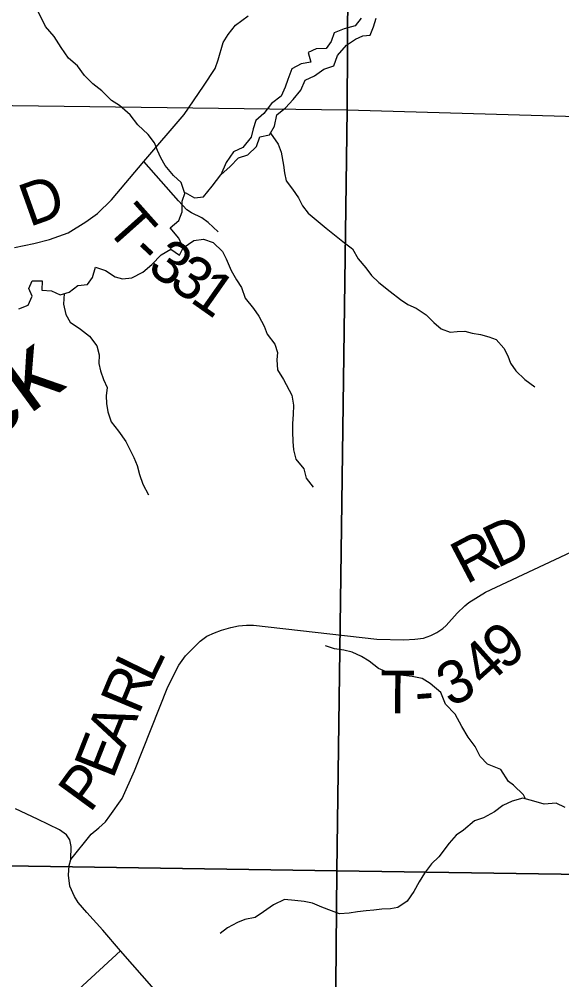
# Model space of a CAD drawing. Extents: x -3.6 to 34, y 0 to 32.8.
# Drawn here: x 0.835 to 1.556, y 30.853 to 32.129 of the extents above; entities that cross this region are included whole.
import ezdxf

# ---------------------------------------------------------------- set-up
doc = ezdxf.new("R2010")
doc.units = 0
for name, color, linetype in [('GM_X_Corporation', 7, 'Continuous'), ('GM_X_County_Road', 7, 'Continuous'), ('GM_X_County_Road_Text', 7, 'Continuous'), ('GM_X_Minor_River', 7, 'Continuous'), ('GM_X_Minor_River_Text', 7, 'Continuous'), ('GM_X_State_Route', 7, 'Continuous'), ('GM_X_Township_Road', 7, 'Continuous'), ('GM_X_Township_Road_Text', 7, 'Continuous')]:
    doc.layers.add(name, color=color, linetype=linetype)

msp = doc.modelspace()

# ---------------------------------------------------------------- linework, layer by layer
at = {"layer": 'GM_X_Corporation'}
for points in [[(1.2753, 32.8429), (0.2894, 32.8429), (0.2807, 32.0992), (0.279, 32.0211), (1.2712, 32.0083)], [(2.2831, 32.8429), (1.2753, 32.8429), (1.2712, 32.0083), (2.2789, 31.9792)], [(0.279, 32.0211), (1.2712, 32.0083), (1.2573, 30.9978), (0.262, 31.0128), (0.2635, 31.0982)], [(1.2712, 32.0083), (2.2789, 31.9792), (2.27, 30.9827), (1.2573, 30.9978)], [(0.262, 31.0128), (1.2573, 30.9978), (1.2483, 29.9822), (0.244, 29.9924), (0.2459, 30.0789)], [(1.2573, 30.9978), (2.27, 30.9827), (2.2535, 29.9602), (1.2483, 29.9822)]]:
    msp.add_lwpolyline(points, close=True, dxfattribs=at)
at = {"layer": 'GM_X_County_Road'}
for points in [[(0.8292, 31.8255), (0.855, 31.8306), (0.8758, 31.8359), (0.9004, 31.8451), (0.9237, 31.8597), (0.9395, 31.8706), (0.9578, 31.8888), (1.001, 31.9395), (1.0545, 32.0021), (1.0804, 32.0395), (1.0955, 32.063), (1.0995, 32.0745), (1.1063, 32.0978), (1.1129, 32.1082), (1.1226, 32.1205), (1.1394, 32.133)], [(0.8918, 30.82), (0.9701, 30.8915)]]:
    msp.add_lwpolyline(points, dxfattribs=at)
at = {"layer": 'GM_X_Minor_River'}
for points in [[(1.0555, 31.8971), (1.0507, 31.9118), (1.0403, 31.9211), (1.0291, 31.9342), (1.0236, 31.9444), (1.0189, 31.9542), (1.0149, 31.9643), (1.0068, 31.9756), (0.9929, 31.9883), (0.9828, 32.0018), (0.9685, 32.014), (0.9578, 32.0207), (0.945, 32.0334), (0.9331, 32.0427), (0.9219, 32.0539), (0.9126, 32.0666), (0.901, 32.077), (0.8913, 32.0909), (0.8819, 32.1056), (0.8703, 32.119), (0.8593, 32.1416)], [(1.1033, 31.9218), (1.1157, 31.933), (1.1265, 31.9446), (1.1393, 31.9486), (1.1506, 31.9594), (1.1549, 31.9724), (1.1681, 31.9749), (1.1744, 31.9867), (1.1776, 32.0016), (1.1892, 32.0109), (1.1992, 32.022), (1.2093, 32.0343), (1.2151, 32.0477), (1.2276, 32.0536), (1.24, 32.0622), (1.2532, 32.0666), (1.2583, 32.0803), (1.2702, 32.0942), (1.2822, 32.102), (1.292, 32.1063), (1.3018, 32.1076), (1.3062, 32.1183), (1.3094, 32.1301)], [(1.2897, 32.1298), (1.2815, 32.1198), (1.2671, 32.1157), (1.2539, 32.1106), (1.2496, 32.0991), (1.2433, 32.0895), (1.23, 32.0893), (1.2191, 32.0842), (1.2227, 32.0714), (1.2098, 32.0693), (1.1974, 32.0626), (1.1923, 32.0485), (1.1887, 32.0382), (1.1836, 32.0263), (1.1705, 32.0166), (1.1604, 32.0032), (1.1496, 31.9939), (1.146, 31.9832), (1.1435, 31.9718), (1.1323, 31.9583), (1.1199, 31.9524), (1.1103, 31.9382), (1.1033, 31.9218)], [(1.1694, 31.9772), (1.1794, 31.9625), (1.1833, 31.952), (1.1863, 31.9346), (1.188, 31.9247), (1.19, 31.9141), (1.1986, 31.9029), (1.2064, 31.8913), (1.2119, 31.8807), (1.2192, 31.871), (1.23, 31.8624), (1.2431, 31.8513), (1.2543, 31.8424), (1.2674, 31.8316), (1.2781, 31.8238), (1.2856, 31.8106), (1.296, 31.7983), (1.3034, 31.7885), (1.3131, 31.7788), (1.3281, 31.7669), (1.3419, 31.7565), (1.3515, 31.7499), (1.3626, 31.7447), (1.376, 31.7362), (1.3861, 31.7258), (1.3961, 31.7176), (1.4079, 31.7132), (1.4174, 31.7138), (1.4273, 31.7143), (1.4372, 31.7118), (1.4482, 31.7101), (1.4593, 31.7069), (1.4692, 31.7033), (1.4793, 31.6917), (1.4844, 31.6815), (1.488, 31.6717), (1.495, 31.6619), (1.5073, 31.6504), (1.5204, 31.6404)], [(0.9329, 31.7858), (0.9368, 31.7995), (0.9498, 31.7948), (0.9629, 31.7867), (0.9724, 31.7838), (0.9849, 31.7851), (0.9996, 31.7926), (1.0116, 31.8027), (1.0239, 31.8158), (1.0367, 31.8232), (1.0482, 31.8154), (1.0533, 31.825), (1.0474, 31.8378), (1.0358, 31.8516), (1.0474, 31.8613), (1.0518, 31.8728), (1.0519, 31.8868), (1.0559, 31.8983), (1.0682, 31.8912), (1.0803, 31.8926), (1.0918, 31.9068), (1.1033, 31.9218)], [(1.0533, 31.8251), (1.0672, 31.8347), (1.0801, 31.8364), (1.0931, 31.8321), (1.1054, 31.8202), (1.1105, 31.8104), (1.1169, 31.7949), (1.1239, 31.7825), (1.1305, 31.7724), (1.1357, 31.7584), (1.1466, 31.7446), (1.1539, 31.7345), (1.1606, 31.7209), (1.1646, 31.7103), (1.1751, 31.6969), (1.1783, 31.6859), (1.1777, 31.6764), (1.1787, 31.6632), (1.1865, 31.6504), (1.1975, 31.6293), (1.1996, 31.6161), (1.1994, 31.6036), (1.1985, 31.5918), (1.1983, 31.5808), (1.1989, 31.5679), (1.1998, 31.5569), (1.2027, 31.5444), (1.2135, 31.5317), (1.2164, 31.5192), (1.2257, 31.5072)], [(0.8349, 31.744), (0.8473, 31.7487), (0.8524, 31.7609), (0.8481, 31.7711), (0.8525, 31.781), (0.8657, 31.7813), (0.8652, 31.7687), (0.8781, 31.7678), (0.8896, 31.7627), (0.9017, 31.7663), (0.9133, 31.7752), (0.9262, 31.7762), (0.9329, 31.7858)], [(0.8949, 31.7643), (0.8944, 31.7503), (0.8972, 31.7366), (0.9031, 31.7265), (0.9169, 31.7169), (0.9289, 31.7076), (0.9386, 31.6948), (0.9414, 31.6831), (0.9412, 31.6714), (0.9433, 31.6615), (0.9473, 31.6502), (0.9524, 31.6397), (0.9511, 31.6286), (0.9512, 31.6184), (0.9533, 31.6074), (0.9577, 31.5942), (0.9674, 31.5815), (0.9768, 31.568), (0.9827, 31.5563), (0.9878, 31.5465), (0.9921, 31.536), (0.995, 31.5239), (0.9998, 31.5111), (1.0072, 31.4972)], [(1.4852, 31.1165), (1.475, 31.1323), (1.4574, 31.1393), (1.4478, 31.1497), (1.4411, 31.1629), (1.4318, 31.1753), (1.4232, 31.1895), (1.4146, 31.2057), (1.4018, 31.2192), (1.3955, 31.2346), (1.3812, 31.2465), (1.3705, 31.2532), (1.3575, 31.256), (1.3461, 31.2573), (1.3347, 31.2583), (1.3221, 31.2626), (1.3125, 31.2666), (1.3002, 31.2763), (1.2903, 31.2826), (1.2776, 31.288), (1.2666, 31.2909), (1.2544, 31.2926), (1.2422, 31.2966)], [(1.5082, 31.0935), (1.5052, 31.0987), (1.4922, 31.1117), (1.4852, 31.1165)], [(1.5607, 31.0821), (1.5489, 31.0876), (1.5327, 31.0862), (1.519, 31.0905), (1.5045, 31.0945), (1.4902, 31.0905), (1.4778, 31.0846), (1.4666, 31.0761), (1.4523, 31.0683), (1.4403, 31.0643), (1.4257, 31.0516), (1.416, 31.045), (1.4067, 31.0346), (1.393, 31.0162), (1.3829, 31.0069), (1.374, 30.9946), (1.3666, 30.9831), (1.3596, 30.9705), (1.3507, 30.9575), (1.3384, 30.9493), (1.3286, 30.9473), (1.3172, 30.9467), (1.3063, 30.9458), (1.2964, 30.9445), (1.2847, 30.9432), (1.2738, 30.9415), (1.2609, 30.9406), (1.2503, 30.9446), (1.2373, 30.9497), (1.2251, 30.9548), (1.2141, 30.9569), (1.2016, 30.9583), (1.188, 30.9596), (1.173, 30.9525), (1.1599, 30.9432), (1.149, 30.9358), (1.135, 30.933), (1.1253, 30.9294), (1.1121, 30.922), (1.1024, 30.9146)]]:
    msp.add_lwpolyline(points, dxfattribs=at)
at = {"layer": 'GM_X_State_Route'}
msp.add_lwpolyline([(1.0145, 30.8408), (0.9701, 30.8915), (0.9463, 30.919), (0.9253, 30.9423), (0.9138, 30.9557), (0.909, 30.9636), (0.9024, 30.9776), (0.9008, 30.9921), (0.9018, 31.0048), (0.9038, 31.0128), (0.9045, 31.0301), (0.9024, 31.0389), (0.8982, 31.0455), (0.8891, 31.0524), (0.8598, 31.0666), (0.8306, 31.0803)], dxfattribs=at)
at = {"layer": 'GM_X_Township_Road'}
for points in [[(1.0998, 31.8464), (1.0863, 31.8587), (1.0778, 31.865), (1.0643, 31.8716), (1.0581, 31.8756), (1.0469, 31.8876), (1.001, 31.9395)], [(0.9038, 31.0128), (0.9311, 31.0463), (0.9412, 31.0551), (0.9499, 31.0629), (0.9559, 31.0707), (0.9721, 31.0937), (0.9884, 31.1305), (1.033, 31.242), (1.0473, 31.2711), (1.0564, 31.2831), (1.0673, 31.2943), (1.0757, 31.3026), (1.0846, 31.3095), (1.0948, 31.314), (1.1042, 31.3175), (1.1163, 31.3209), (1.1269, 31.3233), (1.1375, 31.324), (1.1467, 31.324), (1.3104, 31.3052), (1.3462, 31.3046), (1.361, 31.3052), (1.3724, 31.3068), (1.3824, 31.3102), (1.3903, 31.3144), (1.3982, 31.3196), (1.4026, 31.3237), (1.417, 31.34), (1.4273, 31.3495), (1.4328, 31.354), (1.4549, 31.3678), (1.726, 31.4948)]]:
    msp.add_lwpolyline(points, dxfattribs=at)

# ---------------------------------------------------------------- texts
at = {"layer": 'GM_X_County_Road_Text'}
msp.add_text('D', height=0.0568, rotation=19.7107, dxfattribs=at).set_placement((0.8488, 31.8524))
at = {"layer": 'GM_X_Minor_River_Text'}
msp.add_text('Creek', height=0.0947, rotation=36.301, dxfattribs=at).set_placement((0.6273, 31.4405))
at = {"layer": 'GM_X_Township_Road_Text'}
for s, rotation, p in [('T', 311.7089, (0.9483, 31.8515)), ('-', 316.9331, (0.9805, 31.8158)), ('3', 324.4433, (1.0036, 31.7949)), ('3', 324.8782, (1.0323, 31.7744)), ('1', 324.8759, (1.0607, 31.7544)), ('D', 25.3398, (1.4699, 31.399)), ('R', 27.7608, (1.4292, 31.3776)), ('9', 37.8535, (1.4793, 31.2623)), ('4', 41.8544, (1.454, 31.2396)), ('L', 64.008, (1.0117, 31.2461)), ('3', 25.5545, (1.4078, 31.2147)), ('R', 67.4064, (0.9942, 31.2038)), ('T', 359.6893, (1.315, 31.207)), ('-', 4.5863, (1.3628, 31.207)), ('A', 67.7284, (0.9752, 31.1576)), ('E', 68.441, (0.9597, 31.1183)), ('P', 53.887, (0.9295, 31.0735))]:
    msp.add_text(s, height=0.0568, rotation=rotation, dxfattribs=at).set_placement(p)

doc.saveas('drawing.dxf')
